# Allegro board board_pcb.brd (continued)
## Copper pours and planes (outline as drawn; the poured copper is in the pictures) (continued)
N15026 on TOP (solid shape): 64.9,23.11 64.98,23.11 64.98,23.05 69.28,23.05 69.34,22.99 69.34,21.97 69.09,21.72 64.06,21.72 63.53,22.25 63.53,23.27 63.63,23.37 64.64,23.37
N15026 on TOP (solid shape): 60.76,22.99 60.76,22.83 60.73,22.81 59.56,22.81 59.54,22.78 59.54,22.15 59.41,22.02 58.52,22.02 58.47,22.07 58.47,22.91 58.57,23.01 60.73,23.01
N15026 on BOTTOM (solid shape): 64.77,23.24 64.77,22.23 64.64,22.1 63.63,22.1 63.5,22.23 63.5,23.24 63.63,23.37 64.64,23.37
N15026 on ART06 (solid shape): 60.94,23.21 61.1,23.01 61.34,22.94 61.51,22.97 61.65,23.07 61.72,23.1 62.1,22.94 62.48,23.1 62.56,23.07 62.7,22.97 62.87,22.94 63.11,23.01 63.27,23.21 63.28,23.24 64.9,23.24 65.02,23.11 65.02,21.21 64.9,21.08 62.18,21.08 61.98,21.13 61.77,21.08 58.67,21.08 58.42,21.34 58.42,23.11 58.55,23.24 60.93,23.24
N26661 on TOP (solid shape): 87.63,40.26 87.63,39.75 87.5,39.62 87.38,39.62 87.25,39.5 87.25,38.97 87.2,38.87 87.19,38.76 87.19,37.98 87.22,37.82 87.32,37.68 88.39,36.6 88.39,35.92 88.43,35.78 88.52,35.67 88.52,35.5 88.48,35.42 88.47,35.33 88.47,34.82 88.48,34.74 88.51,34.67 88.48,34.6 88.47,34.52 88.47,34.01 88.48,33.92 88.52,33.84 88.52,33.15 88.77,32.89 88.77,30.23 88.71,30.17 84.39,30.17 84.2,30.35 84.2,31.37 84.58,31.75 86.23,31.75 86.36,31.88 86.36,37.34 87,37.97 87,39.5 86.97,39.52 86.97,40.36 87,40.39 87.5,40.39
N26661 on BOTTOM (solid shape): 88.49,39.9 88.49,36.98 88.14,36.63 88.14,32.13 87.76,31.75 86.49,31.75 86.23,32 86.23,37.47 86.61,37.85 86.61,38.86 87.06,39.31 87.06,40.32 87.12,40.39 88.01,40.39
N27346 on TOP (solid shape): 64.39,34.29 64.39,33.27 64.49,33.17 64.51,33.14 64.54,33.1 64.57,33.07 64.61,33.04 64.64,33.02 64.69,32.97 65.46,32.97 65.79,32.64 71.12,32.64 71.37,32.89 73.41,32.89 73.53,32.77 73.53,31.75 72.77,30.99 66.29,30.99 66.17,31.11 65.96,31.11 65.91,31.17 64.21,31.17 63.12,32.26 65.41,32.26 65.41,32.77 65.02,32.77 65.02,32.26 63.12,32.26 63.12,33.6 63.13,33.62 63.15,33.66 63.17,33.7 63.17,33.75 63.18,33.77 63.18,34.13 63.17,34.15 63.17,34.2 63.15,34.24 63.13,34.28 63.11,34.32 63.07,34.36 63.04,34.38 62.99,34.42 62.94,34.43 62.89,34.43 62.87,34.43 61.58,34.43 61.54,34.47 61.54,34.72 61.55,34.75 61.57,34.76 61.6,34.77 62.87,34.77 62.89,34.77 62.93,34.77 62.97,34.79 63,34.8 63.88,34.8
N30120 on TOP (solid shape): 72.71,15.62 73.65,15.62 73.67,15.61 73.72,15.59 73.77,15.58 73.83,15.57 73.85,15.57 74.36,15.57 74.41,15.56 74.43,15.55 74.43,15.46 74.41,15.44 74.36,15.43 73.85,15.43 73.83,15.43 73.77,15.43 73.74,15.42 73.66,15.42 73.61,15.37 73.53,15.37 73.15,14.99 73.15,14.86 72.64,14.35 71.75,14.35 71.63,14.22 71.63,13.85 71.6,13.81 71.37,13.59 70.99,13.59 70.8,13.78 70.8,14.1 71.37,14.1 71.37,14.48 70.99,14.48 70.99,14.1 70.8,14.1 70.8,15.11 71.37,15.11 71.37,15.49 70.99,15.49 70.99,15.11 70.8,15.11 70.8,15.56 70.87,15.62 72.69,15.62
N30390 on TOP (solid shape): 74.41,15.06 74.43,15.05 74.43,15.02 74.43,14.79 74.44,14.74 74.45,14.7 74.47,14.66 74.5,14.62 74.53,14.58 74.55,14.57 74.55,13.08 74.71,12.92 74.71,12.18 74.65,12.12 73.86,12.12 73.66,12.32 74.55,12.32 74.55,12.7 74.17,12.7 74.17,12.32 73.66,12.32 73.66,14.99 73.74,15.07 74.36,15.07
N30402 on TOP (solid shape): 82.68,20.32 82.68,18.16 81.92,17.4 79.63,17.4 78.99,16.76 77.34,16.76 77.09,16.51 76.83,16.51 76.71,16.64 76.71,17.78 79.12,17.78 79.12,18.29 78.74,18.29 78.74,17.78 78.11,17.78 78.11,18.29 77.72,18.29 77.72,17.78 76.71,17.78 76.71,17.91 77.34,18.54 77.73,18.54 77.76,18.53 77.82,18.52 77.85,18.52 78.36,18.52 78.39,18.52 78.45,18.53 78.48,18.54 78.74,18.54 78.78,18.53 78.84,18.52 78.87,18.52 79.38,18.52 79.4,18.52 79.46,18.53 79.5,18.54 79.88,18.54 79.96,18.62 80.01,18.62 80.07,18.63 80.13,18.64 80.19,18.66 80.24,18.69 80.29,18.73 80.33,18.77 80.37,18.82 80.4,18.87 80.42,18.93 80.43,18.99 80.44,19.05 80.44,19.1 80.64,19.3 80.77,19.3 81.03,19.56 81.03,19.68 81.79,19.68 81.79,20.07 81.28,20.07 81.28,19.68 81.03,19.68 81.04,19.73 81.05,19.78 81.05,19.81 81.05,20.32 81.05,20.35 81.15,20.45 82.55,20.45
N56281 on TOP (solid shape): 84.71,53.09 84.71,52.07 84.81,51.97 84.83,51.94 84.86,51.9 84.89,51.86 84.93,51.83 84.96,51.82 85.01,51.77 85.78,51.77 86.11,51.44 91.44,51.44 91.69,51.69 93.73,51.69 93.85,51.56 93.85,50.04 93.6,49.78 84.71,49.78 83.44,51.05 85.72,51.05 85.72,51.56 85.34,51.56 85.34,51.05 83.44,51.05 83.44,52.39 83.45,52.41 83.47,52.45 83.49,52.5 83.49,52.54 83.5,52.57 83.5,52.92 83.49,52.95 83.49,52.99 83.47,53.04 83.45,53.08 83.43,53.12 83.39,53.15 83.36,53.18 83.31,53.21 83.26,53.22 83.21,53.23 83.19,53.23 81.9,53.23 81.86,53.26 81.86,53.51 81.87,53.54 81.89,53.56 81.92,53.56 83.19,53.56 83.21,53.56 83.25,53.57 83.29,53.58 83.32,53.59 84.2,53.59
N56325 on TOP (solid shape): 88.77,53.98 88.72,53.92 84.3,53.92 84.28,53.9 81.91,53.9 81.89,53.92 81.89,54.15 81.95,54.21 83.19,54.21 83.24,54.22 83.29,54.23 83.64,54.23 84.07,54.66 84.07,54.99 84.26,55.18 88.77,55.18
N16971823 on TOP (solid shape): 110.11,12.7 110.11,2.92 109.73,2.54 102.36,2.54 102.11,2.79 102.11,12.7 102.62,13.21 109.6,13.21
N16971823 on BOTTOM (solid shape): 110.11,12.7 110.11,2.92 109.73,2.54 102.36,2.54 102.11,2.79 102.11,12.7 102.62,13.21 109.6,13.21
N16972859 on TOP (solid shape): 130.94,89.41 130.94,81.28 130.43,80.77 103.12,80.77 102.87,81.03 102.87,89.15 103.38,89.66 130.68,89.66
N16972859 on BOTTOM (solid shape): 129.92,85.09 129.92,81.92 129.16,81.15 103.25,81.15 102.87,81.53 102.87,85.09 103.25,85.47 129.54,85.47
N16973460 on TOP (solid shape): 80.64,9.27 80.64,8.26 80.39,8 78.99,8 78.95,8.01 78.9,8.03 78.87,8.03 78.36,8.03 78.33,8.03 78.27,8.01 78.24,8 77.97,8 77.94,8.01 77.88,8.03 77.85,8.03 77.44,8.03 77.34,8.13 77.34,8.26 78.99,8.26 78.99,8.64 78.61,8.64 78.61,8.26 77.98,8.26 77.98,8.64 77.6,8.64 77.6,8.26 77.34,8.26 77.34,8.89 77.98,8.89 77.98,9.27 77.6,9.27 77.6,8.89 77.34,8.89 77.34,9.4 77.42,9.47 79.12,9.47 79.17,9.53 80.39,9.53
N16973494 on TOP (solid shape): 79.12,12.57 79.12,9.91 78.99,9.78 77.97,9.78 77.94,9.79 77.88,9.8 77.85,9.8 77.44,9.8 77.34,9.91 77.34,10.03 77.98,10.03 77.98,10.54 77.6,10.54 77.6,10.03 77.34,10.03 77.34,12.57 77.47,12.7 78.99,12.7
N16973521 on TOP (solid shape): 82.84,12.81 82.9,12.8 82.93,12.8 83.44,12.8 83.47,12.8 83.53,12.81 83.56,12.83 83.64,12.83 83.69,12.78 84.38,12.78 84.45,12.7 84.45,11.68 84.43,11.67 84.39,11.63 84.35,11.59 84.33,11.56 83.95,11.18 82.68,11.18 81.92,10.41 80.14,10.41 80.01,10.54 80.01,11.68 80.14,11.81 80.9,11.81 81.15,12.06 84.2,12.06 84.2,12.45 83.82,12.45 83.82,12.06 83.19,12.06 83.19,12.57 82.8,12.57 82.8,12.06 82.55,12.06 82.55,12.57 82.17,12.57 82.17,12.06 81.15,12.06 81.89,12.8 81.92,12.8 82.42,12.8 82.45,12.8 82.51,12.81 82.55,12.83 82.81,12.83
N17017201 on TOP (solid shape): 41.35,39.93 41.35,38.18 41.2,38.02 41.2,37.24 41.1,37.13 40.13,37.13 39.98,37.29 39.98,37.47 40.77,37.47 40.77,37.85 40.39,37.85 40.39,37.47 39.98,37.47 39.98,38.33 40.13,38.48 40.77,38.48 41,38.71 41,39.95 41.05,40.01 41.27,40.01
N17048586 on TOP (solid shape): 38.81,50.72 38.81,49.4 38.86,49.35 38.86,49.28 38.63,49.04 38.6,49.03 38.56,49 38.53,48.97 38.5,48.93 38.47,48.85 38.46,48.8 38.46,48.77 38.46,48.26 38.46,48.23 38.47,48.17 38.48,48.14 38.48,47.88 38.47,47.84 38.46,47.78 38.46,47.75 38.46,47.24 38.46,47.21 38.47,47.16 38.48,47.12 38.48,46.28 38.1,46.28 38.07,46.25 38.03,46.25 37.98,46.23 37.93,46.2 37.88,46.17 37.85,46.17 37.82,46.17 37.8,46.18 37.59,46.39 37.59,46.48 38.23,46.48 38.23,46.86 37.85,46.86 37.85,46.48 37.59,46.48 37.59,47.5 38.23,47.5 38.23,47.88 37.85,47.88 37.85,47.5 37.59,47.5 37.59,48.13 38.23,48.13 38.23,48.51 37.85,48.51 37.85,48.13 37.59,48.13 37.59,49.01 37.68,49.1 37.72,49.15 37.75,49.2 37.77,49.26 37.79,49.31 37.8,49.37 37.8,49.44 37.79,49.5 37.77,49.56 37.74,49.62 37.71,49.67 37.67,49.72 37.62,49.77 37.59,49.78 37.59,50.67 37.72,50.8 38.73,50.8
N19175893 on TOP (solid shape): 88.77,48.01 88.77,47.24 88.65,47.12 87.5,47.12 87.25,46.86 87.25,42.93 86.82,42.49 86.73,42.37 86.69,42.21 86.69,42.16 86.28,42.16 86.23,42.22 85.93,42.22 85.6,42.55 85.6,48.01 85.72,48.13 88.65,48.13
N19175893 on BOTTOM (solid shape): 87,42.88 87,41.22 86.79,41.02 86.79,40.49 86.75,40.45 86.75,39.46 86.69,39.4 85.93,39.4 85.83,39.5 85.83,42.27 85.62,42.47 85.62,42.77 85.8,42.95 86.92,42.95
N19573026 on TOP (solid shape): 68.45,35.18 68.4,35.13 63.98,35.13 63.96,35.1 61.59,35.1 61.57,35.13 61.57,35.36 61.63,35.42 62.87,35.42 62.92,35.42 62.97,35.43 63.32,35.43 63.75,35.86 63.75,36.2 63.94,36.38 68.45,36.38

Small or netless copper shapes (teardrops, artwork), in the pictures only: 8 on TOP, 41 on BOTTOM, 8 on GND02, 1 on ART03, 1 on ART06, 1 on ART08

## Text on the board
BOTTOM: 1118915-EMSTAT_PICO_VA_172_PCB ARTWORK BOTTOM
Ref Des/Assembly Bottom: 1118915-EMSTAT_PICO_VA_172_PCB ADB_CENTER
Package Geometry/Pastemask Bottom: 1118915-EMSTAT_PICO_VA_172_PCB PASTEMASK BOTTOM
Ref Des/Silkscreen Bottom: ID4 | ID6 | ID5 | 1118915-EMSTAT_PICO_VA_172_PCB SILKSCREEN BOTTOM
User.Comments: 1118915-EMSTAT_PICO_VA_172_PCB SOLDMASK TOP | 1118915-EMSTAT_PICO_VA_172_PCB SOLDMASK BOTTOM
TOP: 1118915-EMSTAT_PICO_VA_172_PCB ARTWORK TOP
Ref Des/Assembly Top: 1118915-EMSTAT_PICO_VA_172_PCB ADT_CENTER
Package Geometry/Pastemask Top: 1118915-EMSTAT_PICO_VA_172_PCB PASTEMASK TOP
Ref Des/Silkscreen Top: A | ID1 | E | C | B | D | F | G | ID3 | ID2 | 1118915-EMSTAT_PICO_VA_172_PCB SILKSCREEN TOP | EMSTAT_PICO_VA
GND02: 1118915-EMSTAT_PICO_VA_172_PCB GROUND PLANE02
ART03: 1118915-EMSTAT_PICO_VA_172_PCB ARTWORK LAYER03
GND04: 1118915-EMSTAT_PICO_VA_172_PCB GROUND PLANE04
POWER05: 1118915-EMSTAT_PICO_VA_172_PCB POWER PLANE05
ART06: 1118915-EMSTAT_PICO_VA_172_PCB ARTWORK LAYER06
GND07: 1118915-EMSTAT_PICO_VA_172_PCB GROUND PLANE07
ART08: 1118915-EMSTAT_PICO_VA_172_PCB ARTWORK LAYER08
GND09: 1118915-EMSTAT_PICO_VA_172_PCB GROUND PLANE09
DIMENSION: 1--Gerber TOP | 2--GROUND PLANE02 | 3--Gerber LAYER03 | 4--GROUND PLANE04 | 5--POWER PLANE05 | 6--Gerber LAYER06 | 7--GROUND PLANE07 | 8--Gerber LAYER08 | 9--GROUND PLANE09 | 10--Gerber BOTTOM | 1118915-EMSTAT_PICO_VA_172_PCB DRILL CHART
COMPVAL_TYPE_TOP: 1118915-EMSTAT_PICO_VA_172_PCB PANEL
User.11: FIGURE | FINISHED_SIZE | 8.0 | 10.0 | 12.0 | 26.0 | 32.0 | 35.0 | 40.0 | 45.0 | 65.0 | 87.0 | 128.0 | 130.0 | 65.0x25.0 | 80.0x35.0 | 85.0x25.0 | DRILL CHART: TOP to BOTTOM | ALL UNITS ARE IN MILS | TOLERANCE_DRILL | +3.0/-3.0 | +2.0/-2.0 | +5.0/-5.0 | PLATED | NON-PLATED | QTY | 328 | 1326 | 1 | 10 | 9 | 8 | 44 | 28 | 2 | 4 | 1774 | TOTAL HOLES:
